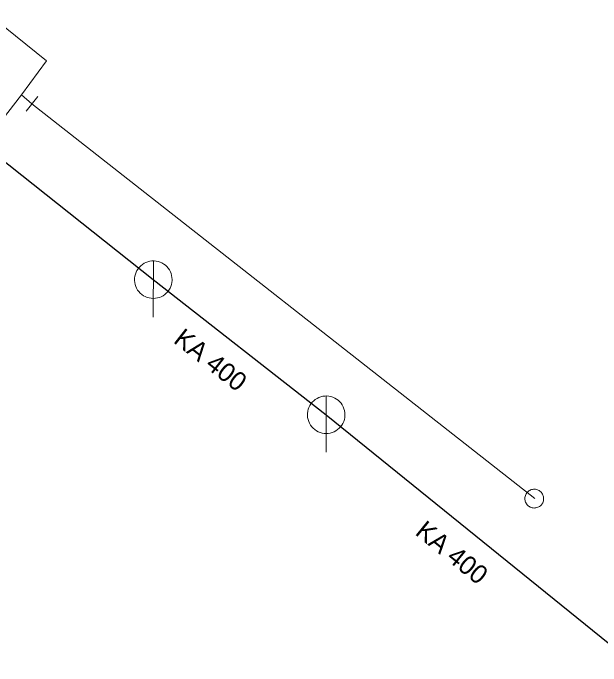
# Model space of a CAD drawing. Extents: x -790267 to -789874, y -989766 to -989454.
# Drawn here: x -790050.43 to -790019.11, y -989631.2 to -989596.43 of the extents above; entities that cross this region are included whole.
import ezdxf

# ---------------------------------------------------------------- set-up
doc = ezdxf.new("R2010")
doc.units = 0
doc.header["$LTSCALE"] = 0.4
doc.layers.add('1', color=7, linetype='Continuous')
for name, color, linetype, lineweight in [('13', 7, 'Continuous', 13), ('14', 7, 'Continuous', 13), ('22', 7, 'Continuous', 13), ('23', 7, 'Continuous', 13), ('34', 7, 'Continuous', 13)]:
    doc.layers.add(name, color=color, linetype=linetype, lineweight=lineweight)

msp = doc.modelspace()

# ---------------------------------------------------------------- linework, layer by layer
at = {"layer": '13'}
for points in [[(-790051.752, -989603.049), (-790049.974, -989600.778), (-790048.645, -989598.973), (-790056.749, -989592.432), (-790055.327, -989590.667)], [(-790049.974, -989600.778), (-790049.426, -989601.256), (-790022.634, -989622.284)]]:
    msp.add_lwpolyline(points, dxfattribs=at)
at = {"layer": '14', "lineweight": 25}
for p, q in [((-790059.488, -989597.498), (-790042.959, -989610.625)), ((-790042.959, -989610.625), (-790033.749, -989617.819)), ((-790033.749, -989617.819), (-790017.22, -989631.198))]:
    msp.add_line(p, q, dxfattribs=at)
at = {"layer": '22'}
for p, q in [((-790042.959, -989612.625), (-790042.958, -989609.625)), ((-790033.749, -989619.819), (-790033.748, -989616.819))]:
    msp.add_line(p, q, dxfattribs=at)
for points in [[(-790041.959, -989610.625), (-790041.964, -989610.516), (-790041.982, -989610.408), (-790042.012, -989610.302), (-790042.052, -989610.201), (-790042.104, -989610.104), (-790042.166, -989610.014), (-790042.238, -989609.931), (-790042.318, -989609.857), (-790042.406, -989609.791), (-790042.5, -989609.736), (-790042.6, -989609.691), (-790042.705, -989609.658), (-790042.812, -989609.636), (-790042.921, -989609.626), (-790043.031, -989609.628), (-790043.139, -989609.642), (-790043.246, -989609.667), (-790043.349, -989609.704), (-790043.447, -989609.753), (-790043.539, -989609.811), (-790043.625, -989609.88), (-790043.702, -989609.957), (-790043.771, -989610.043), (-790043.83, -989610.135), (-790043.878, -989610.233), (-790043.915, -989610.336), (-790043.941, -989610.443), (-790043.955, -989610.551), (-790043.958, -989610.661), (-790043.948, -989610.77), (-790043.927, -989610.877), (-790043.893, -989610.981), (-790043.849, -989611.081), (-790043.794, -989611.176), (-790043.728, -989611.264), (-790043.654, -989611.344), (-790043.571, -989611.416), (-790043.481, -989611.478), (-790043.385, -989611.53), (-790043.283, -989611.571), (-790043.178, -989611.601), (-790043.07, -989611.619), (-790042.96, -989611.625), (-790042.851, -989611.619), (-790042.743, -989611.601), (-790042.638, -989611.572), (-790042.536, -989611.531), (-790042.439, -989611.479), (-790042.349, -989611.417), (-790042.266, -989611.346), (-790042.191, -989611.266), (-790042.126, -989611.178), (-790042.07, -989611.084), (-790042.026, -989610.984), (-790041.992, -989610.88), (-790041.97, -989610.772), (-790041.96, -989610.663)], [(-790032.749, -989617.819), (-790032.754, -989617.71), (-790032.772, -989617.602), (-790032.802, -989617.496), (-790032.842, -989617.395), (-790032.894, -989617.298), (-790032.956, -989617.208), (-790033.028, -989617.125), (-790033.108, -989617.051), (-790033.196, -989616.985), (-790033.29, -989616.93), (-790033.39, -989616.885), (-790033.495, -989616.852), (-790033.602, -989616.83), (-790033.711, -989616.82), (-790033.821, -989616.822), (-790033.929, -989616.836), (-790034.036, -989616.861), (-790034.139, -989616.898), (-790034.237, -989616.947), (-790034.329, -989617.005), (-790034.415, -989617.074), (-790034.492, -989617.151), (-790034.561, -989617.237), (-790034.62, -989617.329), (-790034.668, -989617.427), (-790034.705, -989617.53), (-790034.731, -989617.637), (-790034.745, -989617.745), (-790034.748, -989617.855), (-790034.738, -989617.964), (-790034.717, -989618.071), (-790034.683, -989618.175), (-790034.639, -989618.275), (-790034.584, -989618.37), (-790034.518, -989618.458), (-790034.444, -989618.538), (-790034.361, -989618.61), (-790034.271, -989618.672), (-790034.175, -989618.724), (-790034.073, -989618.765), (-790033.968, -989618.795), (-790033.86, -989618.813), (-790033.75, -989618.819), (-790033.641, -989618.813), (-790033.533, -989618.795), (-790033.428, -989618.766), (-790033.326, -989618.725), (-790033.229, -989618.673), (-790033.139, -989618.611), (-790033.056, -989618.54), (-790032.981, -989618.46), (-790032.916, -989618.372), (-790032.86, -989618.278), (-790032.816, -989618.178), (-790032.782, -989618.074), (-790032.76, -989617.966), (-790032.75, -989617.857)]]:
    msp.add_lwpolyline(points, close=True, dxfattribs=at)
at = {"layer": '23'}
for points in [[(-790022.269, -989622.592), (-790022.239, -989622.548), (-790022.214, -989622.502), (-790022.195, -989622.454), (-790022.18, -989622.404), (-790022.17, -989622.353), (-790022.167, -989622.3), (-790022.168, -989622.248), (-790022.175, -989622.197), (-790022.187, -989622.145), (-790022.204, -989622.096), (-790022.226, -989622.048), (-790022.255, -989622.003), (-790022.286, -989621.962), (-790022.322, -989621.925), (-790022.361, -989621.891), (-790022.406, -989621.86), (-790022.45, -989621.836), (-790022.5, -989621.816), (-790022.548, -989621.801), (-790022.6, -989621.791), (-790022.654, -989621.788), (-790022.706, -989621.789), (-790022.758, -989621.796), (-790022.809, -989621.807), (-790022.857, -989621.825), (-790022.905, -989621.849), (-790022.949, -989621.875), (-790022.99, -989621.907), (-790023.028, -989621.944), (-790023.063, -989621.983), (-790023.092, -989622.026), (-790023.117, -989622.072), (-790023.138, -989622.121), (-790023.152, -989622.17), (-790023.161, -989622.221), (-790023.165, -989622.274), (-790023.164, -989622.326), (-790023.157, -989622.379), (-790023.145, -989622.43)], [(-790022.5, -989621.816), (-790022.548, -989621.801), (-790022.6, -989621.791), (-790022.654, -989621.788), (-790022.706, -989621.789), (-790022.758, -989621.796), (-790022.809, -989621.807), (-790022.857, -989621.825), (-790022.905, -989621.849), (-790022.949, -989621.875), (-790022.99, -989621.907), (-790023.028, -989621.944), (-790023.063, -989621.983), (-790023.092, -989622.026), (-790023.117, -989622.072), (-790023.138, -989622.121), (-790023.152, -989622.17), (-790023.161, -989622.221), (-790023.165, -989622.274), (-790023.164, -989622.326), (-790023.157, -989622.379), (-790023.145, -989622.43), (-790023.128, -989622.478), (-790023.105, -989622.526), (-790023.079, -989622.57), (-790023.045, -989622.612), (-790023.009, -989622.649), (-790022.97, -989622.683), (-790022.927, -989622.712), (-790022.881, -989622.738), (-790022.832, -989622.759), (-790022.782, -989622.773), (-790022.73, -989622.783), (-790022.679, -989622.787), (-790022.626, -989622.784), (-790022.575, -989622.779), (-790022.524, -989622.766), (-790022.474, -989622.749), (-790022.427, -989622.726), (-790022.382, -989622.699)], [(-790023.145, -989622.43), (-790023.128, -989622.478), (-790023.105, -989622.526), (-790023.079, -989622.57), (-790023.045, -989622.612), (-790023.009, -989622.649), (-790022.97, -989622.683), (-790022.927, -989622.712), (-790022.881, -989622.738), (-790022.832, -989622.759), (-790022.782, -989622.773), (-790022.73, -989622.783), (-790022.679, -989622.787), (-790022.626, -989622.784), (-790022.575, -989622.779), (-790022.524, -989622.766), (-790022.474, -989622.749), (-790022.427, -989622.726), (-790022.382, -989622.699), (-790022.341, -989622.666), (-790022.304, -989622.631), (-790022.269, -989622.592), (-790022.239, -989622.548), (-790022.214, -989622.502), (-790022.195, -989622.454), (-790022.18, -989622.404), (-790022.17, -989622.353), (-790022.167, -989622.3), (-790022.168, -989622.248), (-790022.175, -989622.197), (-790022.187, -989622.145), (-790022.204, -989622.096), (-790022.226, -989622.048), (-790022.255, -989622.003), (-790022.286, -989621.962), (-790022.322, -989621.925), (-790022.361, -989621.891), (-790022.406, -989621.86), (-790022.45, -989621.836), (-790022.5, -989621.816)], [(-790022.382, -989622.699), (-790022.341, -989622.666), (-790022.304, -989622.631), (-790022.269, -989622.592)]]:
    msp.add_lwpolyline(points, dxfattribs=at)
at = {"layer": '34'}
msp.add_line((-790049.733, -989601.65), (-790049.117, -989600.862), dxfattribs=at)

# ---------------------------------------------------------------- texts
at = {"layer": '1'}
for rotation, p in [(322, (-790041.94, -989613.939)), (321, (-790029.065, -989624.164))]:
    msp.add_text('KA 400', height=1, rotation=rotation, dxfattribs=at).set_placement(p)

doc.saveas('drawing.dxf')
